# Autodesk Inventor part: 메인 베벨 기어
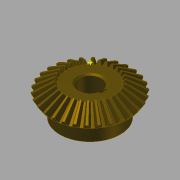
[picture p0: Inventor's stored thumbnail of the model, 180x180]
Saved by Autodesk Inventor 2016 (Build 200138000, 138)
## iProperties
Created: 2014-10
Part Number: 메인 베벨 기어
Material: 강철, 탄소
Document SubType Name: Modeling
Designer: KYOUNG IL JANG
Categories: <?xml version="1.0" encoding="UTF-16"?> <MemberInstance><Categories><FamilyTemplate><FamilyTemplateParameter ValueType="xs:double" Id="1" ObjectReferenceKey="da
Mass: 269.926 g
Surface Area: 108.837 cm^2
Volume: 34.2981 cm^3
Density: 7.87 g/cm^3
Appearance: 얼룩무늬
CustomPartVersion: 1
Author: SeoGD™ [www.esajin.kr]
Revision Number: 1
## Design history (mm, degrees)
node "맨 위 점"
node "메쉬 평면2"
sketch "톱니 본체 스케치"
  geometry: L1 (0, 0)-(28.669, -21.997); L2 (28.669, -21.997)-(31.109, -18.336); L3 (31.109, -18.336)-(0, 0); L4 (30, -20)-(0, 0); L5 (17.219, -13.212)-(18.685, -11.013); L6 (28.669, -21.997)-(17.219, -13.212); L7 (31.109, -18.336)-(18.685, -11.013); L8 (0, -39.387)-(0, 6.564) reference; L9 (0, -20)-(31.109, -20)
  constraints: 16 end point, 4 point on line, 3 perpendicular, 2 collinear, 1 horizontal alignment, 1 vertical alignment
  dimensions: "d0" = 60 diameter of L4.start L8 (= da_de); "d1" = 57.33744 diameter of L1.end L8 (= da_dfe); "d2" = 62.2188 diameter of L2.end L8 (= da_dae); "d3" = 14.4 distance between parallel lines of L2 L5 (= da_b); "d4" = 18.3359 vertical distance of L2.end L1.start (= da_ve)
revolve "톱니 본체" sketch "톱니 본체 스케치" stored, may be unused: angle "d5" = 90 deg
node "시작점"
node "톱니 평면"
sketch "시작 스케치"
  geometry: L1 (0, -23.505)-(0, 10.645) reference; L2 (-0.709, -2.928)-(0.709, -2.928); A1 r 19.188 centre (-19.457, -7.014) between (-0.709, -2.928) and (-3.232, 3.229); A2 r 19.188 centre (19.457, -7.014) between (3.232, 3.229) and (0.709, -2.928); A3 r 57.403 centre (0, -54.083) between (3.232, 3.229) and (-3.232, 3.229); 1 further point
  constraints: 6 point on circle, 3 centre point, 3 symmetric about line, 2 end point, 1 coincident, 1 perpendicular, 1 other
  dimensions: "d7" = 19.18795 radius of A1 (= fd_rr); "d8" = 19.45712 horizontal distance of point (0, -54.083) A1.centre (= fd_x); "d9" = 47.06905 vertical distance of point (0, -54.083) A1.centre (= fd_y); "d57" = 57.40327 radius of A3 (= 0.5 x fd_dva + 0.3 x da_he); "d58" = 51.15527 distance from line of A3.centre L2 (= 0.5 x fd_dva - 1.12 x da_he)
node "끝점"
  node "끝 평면"
sketch "3D 스케치 오른쪽"
  node "Helical Curve Right" dims "d65" = 229.90621 (computed from da_dm, da_delta, da_beta), "d66" = 31.5, "d67" = 60 (= da_de), "d68" = -9.82794 (= -da_delta), "d69" = 8.10972 (computed from fd_loft, da_delta)
node "끝 평면 오른쪽"
sketch "끝 스케치 오른쪽"
  geometry: L1 (0, -41.54)-(0, 13.178) reference; L2 (-0.422, -1.69)-(0.422, -1.69); A1 r 11.427 centre (-11.587, -4.123) between (-0.422, -1.69) and (-1.925, 1.977); A2 r 11.427 centre (11.587, -4.123) between (1.925, 1.977) and (0.422, -1.69); A3 r 34.184 centre (0, -32.153) between (1.925, 1.977) and (-1.925, 1.977); 1 further point
  constraints: 6 point on circle, 3 centre point, 3 symmetric about line, 2 end point, 1 coincident, 1 perpendicular, 1 other
  dimensions: "d70" = 11.58699 horizontal distance of A3.centre A1.centre (computed from fd_x, fd_ratio); "d71" = 28.03028 vertical distance of point (0, -32.153) A1.centre (computed from fd_y, fd_ratio); "d72" = 11.4267 radius of A1 (computed from fd_rr, fd_ratio); "d73" = 30.46369 distance from line of point (0, -32.153) L2 (computed from d58, fd_ratio); "d74" = 34.18446 radius of A3 (computed from d57, fd_ratio)
feature "로프트 오른쪽" sketch "끝 스케치 오른쪽" dims "d75" = 0, "d77" = 0, "d79" = 0, "d80" = 90 deg, "d85" = 20, "d92" = 90 deg, "d93" = 90 deg, "da_teethtype" = 0 [user parameter]
sketch "3D 스케치 왼쪽"
  node "Helical Curve Left" dims "d26" = 229.90621 (computed from da_dm, da_delta, da_beta), "d27" = 8.10972 (computed from fd_loft, da_delta), "d28" = 60 (= da_de), "d29" = -9.82794 (= -da_delta)
node "끝 평면 왼쪽"
sketch "끝 스케치 왼쪽" dims "d56" = 10.3728 (derived)
  geometry: L1 (0, -43.753)-(0, 15.405) reference; L2 (-0.422, -1.678)-(0.422, -1.678); A1 r 11.427 centre (-11.587, -4.111) between (-0.422, -1.678) and (-1.925, 1.988); A2 r 11.427 centre (11.587, -4.111) between (1.925, 1.988) and (0.422, -1.678); A3 r 34.184 centre (0, -32.142) between (1.925, 1.988) and (-1.925, 1.988); 2 further points; 1 other entity
  constraints: 6 point on circle, 3 centre point, 3 symmetric about line, 2 end point, 1 coincident, 2 other
  dimensions: "d30" = 11.4267 radius of A1 (computed from fd_rr, fd_ratio); "d31" = 11.58699 horizontal distance of point (0, -32.142) A1.centre (computed from fd_x, fd_ratio); "d32" = 28.03028 vertical distance of A1.centre point (0, -32.142) (computed from fd_y, fd_ratio); "d61" = 34.18446 radius of A3 (computed from d57, fd_ratio); "d62" = 30.46369 distance from line of point (0, -32.142) L2 (computed from d58, fd_ratio)
feature "로프트 왼쪽" sketch "끝 스케치 왼쪽" dims "d35" = 0, "d37" = 0, "d39" = 0, "d40" = 90 deg, "d84" = 10, "d90" = 90 deg, "d91" = 90 deg, "da_teethtype" = 0 [user parameter]
sketch "본체 스케치"
  geometry: L1 (0, -35.038)-(0, -19.531) reference; L2 (28.669, -21.997)-(17.219, -13.212) reference; L3 (17.219, -13.212)-(0, -13.212); L4 (28.669, -21.997)-(0, -21.997)
  constraints: 4 end point, 2 perpendicular, 2 point on line
revolve "본체 고정" sketch "본체 스케치" stored, may be unused: angle "d46" = 90 deg
feature "피치 지름" dims angle "d47" = 90 deg
sketch "스케치8"
  geometry: C1 r 22.5 at (0, 0); 1 further point
  constraints: 1 centre point, 1 coincident
  dimensions: "d94" = 45 diameter of C1
extrude "돌출1" join sketch "스케치8" distance "d95" = 13; taper "d96" = 0 deg
sketch "스케치9"
  geometry: 1 further point
hole "구멍1" sketch "스케치9" at (0, 0) diameter "d97" = 17; stored, may be unused: countersink angle "d101" = 90 deg, drill point angle "d103" = 118 deg; dims "d98" = 6, "d99" = 4, "d100" = 2, "d102" = 8
sketch "스케치10"
  geometry: L1 (8.124, 2.5)-(10.8, 2.5); L2 (10.8, 2.5)-(10.8, -2.5); L3 (10.8, -2.5)-(8.124, -2.5); A1 r 8.5 centre (0, 0) between (8.124, 2.5) and (8.124, -2.5) reference; 1 further point
  constraints: 6 end point, 2 parallel, 2 point on circle, 1 horizontal, 1 perpendicular
  dimensions: "d104" = 5 distance of L1.end L2.end; "d112" = 19.3 dimension on A1 L2
extrude "돌출2" cut sketch "스케치10" stored distance "d106" = 10; taper "d107" = 0 deg
chamfer "모따기1" distance "d108" = 1; stored, may be unused: second distance "d109" = 2, angle "d110" = 45 deg
fillet "모깎기1" dims "d111" = 2
body "Solid1"
feature "로프트" dims "d17" = 0, "d18" = 90 deg, "d19" = 0, "d20" = 90 deg, "d89" = 0, "da_teethtype" = 0 [user parameter]
pattern_circular "원형 패턴" dims angle "d22" = 360 deg, "d88" = 0, "da_teethtype" = 0 [user parameter]
pattern_circular "원형 패턴 오른쪽" dims angle "d82" = 360 deg, "da_teethtype" = 0 [user parameter]
pattern_circular "원형 패턴 왼쪽" dims angle "d42" = 360 deg, "da_teethtype" = 0 [user parameter]
sketch "끝 스케치"
  geometry: L1 (0, -15.359)-(0, 6.983) reference; L2 (-0.422, -1.69)-(0.422, -1.69); A1 r 11.427 centre (-11.587, -4.123) between (-0.422, -1.69) and (-1.925, 1.977); A2 r 11.427 centre (11.587, -4.123) between (1.925, 1.977) and (0.422, -1.69); A3 r 34.184 centre (0, -32.153) between (1.925, 1.977) and (-1.925, 1.977); 1 further point
  constraints: 6 point on circle, 3 centre point, 3 symmetric about line, 2 end point, 1 coincident, 1 other
  dimensions: "d12" = 11.4267 radius of A1 (computed from fd_rr, fd_ratio); "d15" = 11.58699 horizontal distance of A1.centre point (0, -32.153) (computed from fd_x, fd_ratio); "d16" = 28.03028 vertical distance of A1.centre point (0, -32.153) (computed from fd_y, fd_ratio); "d59" = 34.18446 radius of A3 (computed from d57, fd_ratio); "d60" = 30.46369 distance from line of A3.centre L2 (computed from d58, fd_ratio)
sketch "Sketch6"
  geometry: L1 (30, -20)-(0, 0) reference; L2 (0, -37.8)-(0, 6.3) reference
body "Srf1"
other parameters: "da_b" = 14.4 [user parameter; used in 2 equation terms], "da_de" = 60 [user parameter; used in 4 equation terms], "da_dae" = 62.2188 [user parameter; used in 2 equation terms], "da_dfe" = 57.33744 [user parameter; used in 1 equation term], "da_le" = 36.05551 [user parameter; used in 1 equation term], "da_omega" = 90 deg [user parameter; used in 1 equation term], "da_beta" = 0 [user parameter; used in 2 equation terms], "da_delta" = 9.82794 [user parameter; used in 8 equation terms], "da_alpha" = 20 deg [user parameter; used in 2 equation terms], "da_he" = 4.4 [user parameter; used in 4 equation terms], "da_ve" = 18.3359 [user parameter; used in 1 equation term], "fd_dv" = 108.16654 (computed from da_de, da_delta) [user parameter; used in 1 equation term], "fd_dva" = 112.16654 (computed from da_dae, da_delta) [user parameter; used in 3 equation terms], "fd_dvb" = 101.6433 (computed from fd_dv, da_alpha) [user parameter; used in 2 equation terms], "da_zv" = 540.83269 [user parameter; used in 1 equation term], "fd_loft" = 14.62 (= da_b + 0.05 x da_he) [user parameter; used in 4 equation terms], "fd_ratio" = 5.95514 (computed from da_le, fd_loft) [user parameter; used in 15 equation terms], "fd_rr" = 19.18795 (computed from fd_dd, fd_dvb) [user parameter; used in 6 equation terms], "fd_angle" = 0.29367 (computed from da_zv) [user parameter; used in 4 equation terms], "fd_x1" = 1.58802 (computed from da_dvw, fd_angle) [user parameter; used in 1 equation term], "fd_y1" = 54.05995 (computed from da_dvw, fd_angle) [user parameter; used in 1 equation term], "fd_x2" = 17.8691 (computed from fd_rr, fd_angle2, fd_angle) [user parameter; used in 1 equation term], "fd_y2" = 6.9909 (computed from fd_rr, fd_angle2, fd_angle) [user parameter; used in 1 equation term], "fd_x" = 19.45712 (= fd_x1 + fd_x2) [user parameter; used in 4 equation terms], "fd_y" = 47.06905 (= fd_y1 - fd_y2) [user parameter; used in 4 equation terms], "fd_angle2" = 3.43555 (computed from fd_dvb, fd_dd, da_alpha) [user parameter; used in 2 equation terms], "fd_dd" = 108.64654 (= fd_dva - 0.8 x da_he) [user parameter; used in 2 equation terms], "da_dvw" = 108.16654 [user parameter; used in 2 equation terms], "d11" = 14.62 (= fd_loft), "da_dm" = 48.01848 [user parameter; used in 2 equation terms], "da_x" = 0 [user parameter], "da_m" = 2 [user parameter], "d48" = 0, "d49" = 0, "d50" = 90 deg (= da_omega), "d51" = 6 deg (computed from da_z), "d52" = 0, "d53" = 0, "d54" = 0
